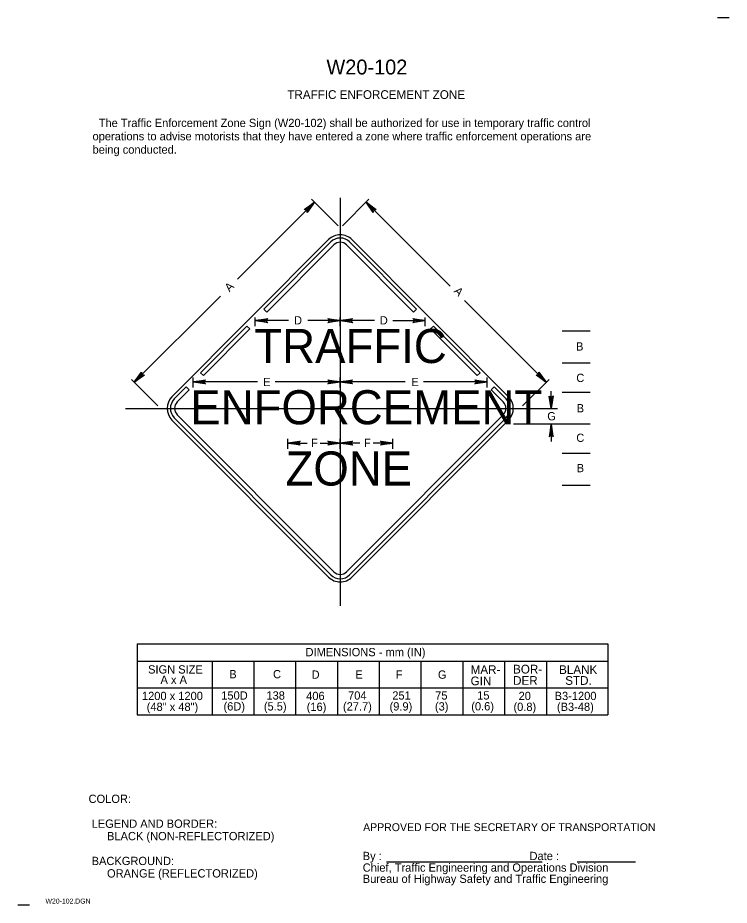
# Model space of a CAD drawing. Extents: x 2147483.661 to 2147484.365, y 2147483.66 to 2147484.539.
import ezdxf

# ---------------------------------------------------------------- set-up
doc = ezdxf.new("R2010")
doc.units = 0
for name, color, linetype in [('1', 7, 'Continuous'), ('2', 7, 'Continuous'), ('3', 7, 'Continuous'), ('63', 7, 'Continuous')]:
    doc.layers.add(name, color=color, linetype=linetype)

# ---------------------------------------------------------------- blocks, each defined once
blk = doc.blocks.new('RARROW')
at = {"layer": '3'}
for p, q in [((-17.248, 2.28), (-18.132, 3.077)), ((-18.132, 3.077), (0, 0)), ((0, 0), (-18.132, -3.033)), ((-17.248, 2.28), (-16.605, 0.966)), ((0, 0), (-17.248, 2.28)), ((-17.198, -2.164), (0, 0)), ((-16.605, 0.966), (0, 0)), ((0, 0), (-16.592, -0.864)), ((-18.132, -3.033), (-17.198, -2.164)), ((-16.592, -0.864), (-17.198, -2.164))]:
    blk.add_line(p, q, dxfattribs=at)

msp = doc.modelspace()

# ---------------------------------------------------------------- linework, layer by layer
at = {"layer": '1'}
for p, q in [((2147483.97056, 2147484.3166), (2147483.90429, 2147484.25012)), ((2147484.05547, 2147484.25012), (2147483.98919, 2147484.3166)), ((2147483.90725, 2147484.24716), (2147483.97353, 2147484.31365)), ((2147483.98623, 2147484.31365), (2147484.05251, 2147484.24716)), ((2147483.90429, 2147484.25012), (2147483.90725, 2147484.24716)), ((2147484.05251, 2147484.24716), (2147484.05547, 2147484.25012)), ((2147483.88752, 2147484.2333), (2147483.84146, 2147484.1871)), ((2147483.84442, 2147484.18414), (2147483.89049, 2147484.23035)), ((2147483.89049, 2147484.23035), (2147483.88752, 2147484.2333)), ((2147484.07223, 2147484.2333), (2147484.06927, 2147484.23035)), ((2147484.06927, 2147484.23035), (2147484.11533, 2147484.18414)), ((2147484.11829, 2147484.1871), (2147484.07223, 2147484.2333)), ((2147483.84146, 2147484.1871), (2147483.84442, 2147484.18414)), ((2147484.11533, 2147484.18414), (2147484.11829, 2147484.1871)), ((2147483.8155, 2147484.16105), (2147483.82742, 2147484.17301)), ((2147483.83038, 2147484.17006), (2147483.81846, 2147484.1581)), ((2147483.82742, 2147484.17301), (2147483.83038, 2147484.17006)), ((2147484.12937, 2147484.17006), (2147484.13234, 2147484.17301)), ((2147484.1413, 2147484.1581), (2147484.12937, 2147484.17006)), ((2147484.13234, 2147484.17301), (2147484.14426, 2147484.16105)), ((2147483.97056, 2147483.98694), (2147483.8155, 2147484.14248)), ((2147483.81846, 2147484.14544), (2147483.97353, 2147483.98989)), ((2147483.98623, 2147483.98989), (2147484.1413, 2147484.14544)), ((2147484.14426, 2147484.14248), (2147483.98919, 2147483.98694)), ((2147484.2448, 2147483.91842), (2147484.2448, 2147483.8483)), ((2147484.02574, 2147483.70259), (2147484.17988, 2147483.70259)), ((2147484.21443, 2147483.70259), (2147484.27221, 2147483.70259))]:
    msp.add_line(p, q, dxfattribs=at)
for centre, radius, start, end in [((2147483.97988, 2147484.30731), 0.01315, 44.91172, 135.08828), ((2147483.97988, 2147484.30731), 0.00897, 44.91172, 135.08828), ((2147483.82481, 2147484.15177), 0.01315, 135.08828, 224.91172), ((2147483.82481, 2147484.15177), 0.00897, 135.08828, 224.91172), ((2147484.13494, 2147484.15177), 0.00897, 315.08828, 44.91172), ((2147484.13494, 2147484.15177), 0.01315, 315.08828, 44.91172), ((2147483.97988, 2147483.99622), 0.01315, 224.91172, 315.08828), ((2147483.97988, 2147483.99622), 0.00897, 224.91172, 315.08828)]:
    msp.add_arc(centre, radius, start, end, dxfattribs=at)
at = {"layer": '3'}
for p, q in [((2147483.97988, 2147484.36026), (2147483.97988, 2147483.95626)), ((2147483.87818, 2147484.27982), (2147483.95434, 2147484.35597)), ((2147483.94422, 2147484.34876), (2147483.95434, 2147484.35597)), ((2147483.95434, 2147484.35597), (2147483.94502, 2147484.3488)), ((2147483.94594, 2147484.34849), (2147483.95434, 2147484.35597)), ((2147483.95434, 2147484.35597), (2147483.94682, 2147484.34763)), ((2147483.95434, 2147484.35597), (2147483.94711, 2147484.34587)), ((2147483.94714, 2147484.34673), (2147483.95434, 2147484.35597)), ((2147483.97773, 2147484.33257), (2147483.95145, 2147484.35886)), ((2147483.98203, 2147484.33257), (2147484.00831, 2147484.35886)), ((2147484.08862, 2147484.27277), (2147484.00542, 2147484.35597)), ((2147483.94502, 2147484.3488), (2147483.94422, 2147484.34876)), ((2147483.94502, 2147484.3488), (2147483.94594, 2147484.34849)), ((2147483.94682, 2147484.34763), (2147483.94714, 2147484.34673)), ((2147483.94711, 2147484.34587), (2147483.94714, 2147484.34673)), ((2147483.96831, 2147484.31885), (2147483.81324, 2147484.1633)), ((2147484.14652, 2147484.1633), (2147483.99145, 2147484.31885)), ((2147483.86135, 2147484.26298), (2147483.77593, 2147484.17756)), ((2147484.10292, 2147484.25846), (2147484.18383, 2147484.17756)), ((2147483.89577, 2147484.23323), (2147483.89577, 2147484.24173)), ((2147483.92873, 2147484.23863), (2147483.89577, 2147484.23863)), ((2147483.97988, 2147484.23863), (2147483.94774, 2147484.23863)), ((2147483.97988, 2147484.23323), (2147483.97988, 2147484.24173)), ((2147484.01367, 2147484.23863), (2147483.97988, 2147484.23863)), ((2147484.03188, 2147484.23863), (2147484.06398, 2147484.23863)), ((2147484.06398, 2147484.23323), (2147484.06398, 2147484.24173)), ((2147484.22734, 2147484.22814), (2147484.1998, 2147484.22814)), ((2147484.22734, 2147484.19657), (2147484.1998, 2147484.19657)), ((2147483.77593, 2147484.17756), (2147483.78316, 2147484.18766)), ((2147483.78312, 2147484.1868), (2147483.77593, 2147484.17756)), ((2147483.77593, 2147484.17756), (2147483.78345, 2147484.1859)), ((2147483.78432, 2147484.18504), (2147483.77593, 2147484.17756)), ((2147483.78605, 2147484.18477), (2147483.77593, 2147484.17756)), ((2147483.77593, 2147484.17756), (2147483.78525, 2147484.18473)), ((2147483.78316, 2147484.18766), (2147483.78312, 2147484.1868)), ((2147483.78345, 2147484.1859), (2147483.78312, 2147484.1868)), ((2147483.78525, 2147484.18473), (2147483.78432, 2147484.18504)), ((2147483.78525, 2147484.18473), (2147483.78605, 2147484.18477)), ((2147483.79932, 2147484.15417), (2147483.77304, 2147484.18045)), ((2147483.83427, 2147484.17258), (2147483.83427, 2147484.18246)), ((2147483.89799, 2147484.17797), (2147483.83427, 2147484.17797)), ((2147483.97988, 2147484.17797), (2147483.91538, 2147484.17797)), ((2147483.97988, 2147484.17258), (2147483.97988, 2147484.18246)), ((2147484.04401, 2147484.17797), (2147483.97988, 2147484.17797)), ((2147484.12548, 2147484.17797), (2147484.06221, 2147484.17797)), ((2147484.12548, 2147484.17258), (2147484.12548, 2147484.18246)), ((2147484.16043, 2147484.15417), (2147484.18672, 2147484.18045)), ((2147484.18877, 2147484.15175), (2147484.18877, 2147484.16878)), ((2147484.22734, 2147484.16755), (2147484.1998, 2147484.16755)), ((2147483.76723, 2147484.15175), (2147484.17828, 2147484.15175)), ((2147484.17828, 2147484.15175), (2147484.195, 2147484.15175)), ((2147483.96831, 2147483.98469), (2147483.81324, 2147484.14023)), ((2147484.14652, 2147484.14023), (2147483.99145, 2147483.98469)), ((2147484.22734, 2147484.13598), (2147484.1516, 2147484.13598)), ((2147484.18877, 2147484.13597), (2147484.18877, 2147484.11894)), ((2147483.92784, 2147484.11175), (2147483.92784, 2147484.12163)), ((2147483.92784, 2147484.11734), (2147483.94703, 2147484.11734)), ((2147483.95998, 2147484.11734), (2147483.97988, 2147484.11734)), ((2147483.97988, 2147484.11175), (2147483.97988, 2147484.12163)), ((2147483.99942, 2147484.11734), (2147483.97988, 2147484.11734)), ((2147484.03192, 2147484.11734), (2147484.01256, 2147484.11734)), ((2147484.03192, 2147484.11175), (2147484.03192, 2147484.12163)), ((2147484.22734, 2147484.10697), (2147484.1998, 2147484.10697)), ((2147484.22734, 2147484.0754), (2147484.1998, 2147484.0754)), ((2147483.77873, 2147483.91842), (2147484.2448, 2147483.91842)), ((2147483.77873, 2147483.91842), (2147483.77873, 2147483.8483)), ((2147484.2448, 2147483.90117), (2147483.77873, 2147483.90117)), ((2147483.85289, 2147483.90117), (2147483.85289, 2147483.8483)), ((2147483.89428, 2147483.90117), (2147483.89428, 2147483.8483)), ((2147483.93567, 2147483.90117), (2147483.93567, 2147483.8483)), ((2147483.97706, 2147483.90117), (2147483.97706, 2147483.8483)), ((2147484.01845, 2147483.90117), (2147484.01845, 2147483.8483)), ((2147484.05984, 2147483.90117), (2147484.05984, 2147483.8483)), ((2147484.10123, 2147483.90117), (2147484.10123, 2147483.8483)), ((2147484.10123, 2147483.90117), (2147484.10123, 2147483.8483)), ((2147484.14262, 2147483.90117), (2147484.14262, 2147483.8483)), ((2147484.18401, 2147483.90117), (2147484.18401, 2147483.8483)), ((2147483.77873, 2147483.87487), (2147484.2448, 2147483.87487)), ((2147483.77873, 2147483.8483), (2147484.2448, 2147483.8483))]:
    msp.add_line(p, q, dxfattribs=at)
for centre, start, end in [((2147483.97988, 2147484.30731), 44.91172, 135.08828), ((2147483.82481, 2147484.15177), 135.08828, 224.91172), ((2147484.13494, 2147484.15177), 315.08828, 44.91172), ((2147483.97988, 2147483.99622), 224.91172, 315.08828)]:
    msp.add_arc(centre, 0.01634, start, end, dxfattribs=at)
at = {"layer": '63'}
for p, q in [((2147484.36509, 2147484.53857), (2147484.35361, 2147484.53857)), ((2147483.67202, 2147483.65971), (2147483.66053, 2147483.65971))]:
    msp.add_line(p, q, dxfattribs=at)

# ---------------------------------------------------------------- block references
at = {"layer": '3'}
for p, xscale, yscale, rotation in [((2147484.00542, 2147484.35597), 0.000675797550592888, 0.0006684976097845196, 135), ((2147483.89577, 2147484.23863), 0.000675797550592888, 0.0006684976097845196, 180), ((2147483.97988, 2147484.23863), 0.000675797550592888, 0.0006684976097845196, 180), ((2147484.18383, 2147484.17756), 0.0006757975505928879, 0.0006684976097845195, -45), ((2147483.83427, 2147484.17797), 0.000675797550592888, 0.0006684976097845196, 180), ((2147483.97988, 2147484.17797), 0.000675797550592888, 0.0006684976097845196, 180), ((2147484.18877, 2147484.15175), 0.000675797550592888, 0.0006684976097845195, -89.93923132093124), ((2147484.18877, 2147484.13597), 0.000675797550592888, -0.0006684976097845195, 89.93923132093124), ((2147483.92784, 2147484.11734), 0.000675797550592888, 0.0006684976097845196, 180), ((2147483.97988, 2147484.11734), 0.000675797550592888, 0.0006684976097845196, 180)]:
    msp.add_blockref('RARROW', p, dxfattribs=dict(at, xscale=xscale, yscale=yscale, rotation=rotation))
at = {"layer": '3', "xscale": 0.000675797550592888, "yscale": 0.0006684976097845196}
for p in [(2147483.97988, 2147484.23863), (2147484.06398, 2147484.23863), (2147483.97988, 2147484.17797), (2147484.12548, 2147484.17797), (2147483.97988, 2147484.11734), (2147484.03192, 2147484.11734)]:
    msp.add_blockref('RARROW', p, dxfattribs=at)

# ---------------------------------------------------------------- texts
at = {"layer": '1'}
for s, height, p in [('W20-102', 0.014764, (2147483.96621, 2147484.48238)), ('TRAFFIC ENFORCEMENT ZONE', 0.0086122, (2147483.92749, 2147484.45819)), ('COLOR:', 0.008201, (2147483.73066, 2147483.76101)), (' LEGEND AND BORDER:', 0.0082013, (2147483.73066, 2147483.7364)), ('APPROVED FOR THE SECRETARY OF TRANSPORTATION', 0.0077928, (2147484.00256, 2147483.73312)), ('      BLACK (NON-REFLECTORIZED)', 0.0082013, (2147483.73066, 2147483.7241)), ('By :                                                Date :', 0.0082013, (2147484.00215, 2147483.70441)), (' BACKGROUND:', 0.0082013, (2147483.73066, 2147483.6995)), ('Chief, Traffic Engineering and Operations Division', 0.0082013, (2147484.00215, 2147483.69293)), ('      ORANGE (REFLECTORIZED)', 0.0082013, (2147483.73066, 2147483.68719)), ('Bureau of Highway Safety and Traffic Engineering', 0.0082013, (2147484.00215, 2147483.68186)), ('W20-102.DGN', 0.0049213, (2147483.68801, 2147483.66135))]:
    msp.add_text(s, height=height, dxfattribs=at).set_placement(p)
at = {"layer": '2'}
for s, height, p in [('  The Traffic Enforcement Zone Sign (W20-102) shall be authorized for use in temporary traffic control', 0.00820126, (2147483.73459, 2147484.43034)), ('operations to advise motorists that they have entered a zone where traffic enforcement operations are', 0.00820126, (2147483.73459, 2147484.41714)), ('being conducted. ', 0.0082013, (2147483.73459, 2147484.40394))]:
    msp.add_text(s, height=height, dxfattribs=at).set_placement(p)
at = {"layer": '3'}
for s, rotation, p in [('A', 45, (2147483.87019, 2147484.26669)), ('A', 315, (2147484.09177, 2147484.26721)), ('D', 360, (2147483.93413, 2147484.23486)), ('D', 360, (2147484.01907, 2147484.23486)), ('E', 360, (2147484.0504, 2147484.17378)), ('F', 360, (2147484.00338, 2147484.1136))]:
    msp.add_text(s, height=0.00817, rotation=rotation, dxfattribs=at).set_placement(p)
for s, height, p in [('TRAFFIC', 0.033756, (2147483.89479, 2147484.19663)), ('B', 0.00817, (2147484.21343, 2147484.20898)), ('C', 0.00817, (2147484.21366, 2147484.17786)), ('E', 0.00817, (2147483.90358, 2147484.17378)), ('ENFORCEMENT', 0.0337564, (2147483.83138, 2147484.13598)), ('B', 0.00817, (2147484.21405, 2147484.14784)), ('G', 0.00817, (2147484.18488, 2147484.1399)), ('C', 0.00817, (2147484.21366, 2147484.11857)), ('F', 0.00817, (2147483.95105, 2147484.1136)), ('ZONE', 0.033756, (2147483.92565, 2147484.07534)), ('B', 0.00817, (2147484.21405, 2147484.08854)), ('DIMENSIONS - mm (IN)', 0.0082012, (2147483.9455, 2147483.90629)), ('SIGN SIZE', 0.008201, (2147483.78958, 2147483.88916)), ('MAR-', 0.008622, (2147484.10899, 2147483.88875)), ('BOR-', 0.008622, (2147484.15103, 2147483.8892)), ('BLANK', 0.008622, (2147484.19661, 2147483.88876)), ('A x A', 0.008201, (2147483.80188, 2147483.8789)), ('B', 0.00819, (2147483.87001, 2147483.88446)), ('C', 0.00819, (2147483.91334, 2147483.88446)), ('D', 0.00819, (2147483.95151, 2147483.88402)), ('E', 0.00819, (2147483.99477, 2147483.88402)), ('F', 0.00819, (2147484.03479, 2147483.88402)), ('G', 0.00819, (2147484.07661, 2147483.88402)), ('GIN', 0.008622, (2147484.10899, 2147483.87754)), ('DER', 0.008622, (2147484.15103, 2147483.87799)), ('STD.', 0.008622, (2147484.20265, 2147483.87798)), ('1200 x 1200', 0.0081926, (2147483.78356, 2147483.8629)), ('150D', 0.008193, (2147483.86206, 2147483.86334)), ('138', 0.008193, (2147483.90679, 2147483.86335)), ('406', 0.008193, (2147483.94617, 2147483.8629)), ('704', 0.008193, (2147483.98763, 2147483.86334)), ('251', 0.008193, (2147484.03141, 2147483.86334)), ('75', 0.008193, (2147484.0739, 2147483.86334)), ('15', 0.008193, (2147484.11546, 2147483.86344)), ('20', 0.008193, (2147484.15648, 2147483.86291)), ('B3-1200', 0.008193, (2147484.1922, 2147483.86292)), ('(48" x 48")', 0.0081926, (2147483.78823, 2147483.85212)), ('(6D)', 0.008193, (2147483.86428, 2147483.85256)), ('(5.5)', 0.008193, (2147483.90423, 2147483.85257)), ('(16)', 0.008193, (2147483.94667, 2147483.85212)), ('(27.7)', 0.008193, (2147483.98258, 2147483.85256)), ('(9.9)', 0.008193, (2147484.0287, 2147483.85256)), ('(3)', 0.008193, (2147484.07364, 2147483.85256)), ('(0.6)', 0.008193, (2147484.10962, 2147483.85266)), ('(0.8)', 0.008193, (2147484.15141, 2147483.85213)), ('(B3-48)', 0.008193, (2147484.19445, 2147483.85214))]:
    msp.add_text(s, height=height, dxfattribs=at).set_placement(p)

doc.saveas('drawing.dxf')
